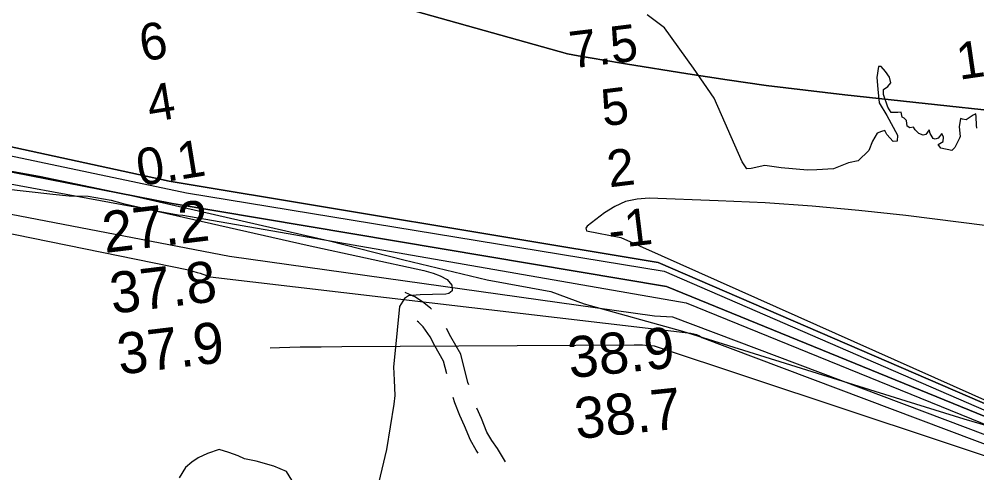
# Model space of a CAD drawing. Extents: x 3219052 to 3256913, y 800770 to 826146.
# Drawn here: x 3226376 to 3227938, y 812303 to 813043 of the extents above; entities that cross this region are included whole.
import ezdxf

# ---------------------------------------------------------------- set-up
doc = ezdxf.new("R2010")
doc.units = 0
for name, color, linetype in [('V-RIVR-EDGE', 7, 'Continuous'), ('V-RIVR-RANG', 7, 'Continuous'), ('V-ROAD-CNTR', 7, 'Continuous'), ('V-SITE-VEGE', 7, 'Continuous'), ('V-TOPO-DPTH', 7, 'Continuous'), ('V-TOPO-MAJR', 7, 'Continuous'), ('V-TOPO-MINR', 7, 'Continuous'), ('V-TOPO-WATR', 7, 'Continuous')]:
    doc.layers.add(name, color=color, linetype=linetype)

msp = doc.modelspace()

# ---------------------------------------------------------------- linework, layer by layer
at = {"layer": 'V-RIVR-EDGE'}
for points in [[(3227676.5, 812797.1), (3227661.4, 812796.4), (3227618.4, 812800.4), (3227591.9, 812803.7), (3227569.3, 812799), (3227562.2, 812798.6), (3227554.7, 812809.7), (3227509.1, 812913.8), (3227475.7, 812962.9), (3227428, 813028.6), (3227400, 813050)], [(3227937.6, 812864.9), (3227937.2, 812870), (3227936.4, 812883.5), (3227935.6, 812888.2), (3227931.7, 812886.3), (3227920.2, 812878.4), (3227913.9, 812879.6), (3227911.1, 812880.8), (3227908.7, 812866.9), (3227910.2, 812851.1), (3227909.4, 812848.4), (3227901.5, 812833.4), (3227896.7, 812828.2), (3227879, 812832.2), (3227874.6, 812838.2), (3227882.5, 812843.3), (3227883, 812850.4), (3227880.2, 812855.9), (3227874.7, 812848.4), (3227869.5, 812846.9), (3227866.4, 812848.1), (3227861.6, 812856), (3227859.7, 812862.3), (3227854.5, 812854.4), (3227850.2, 812853.6), (3227843, 812856), (3227836.7, 812862.4), (3227834, 812866.7), (3227828, 812865.6), (3227823.7, 812868.3), (3227822.9, 812877.4), (3227819, 812881), (3227815.8, 812883), (3227814.3, 812890.9), (3227808.7, 812890.5), (3227797.7, 812890.5), (3227792.2, 812898.9), (3227785.1, 812919.8), (3227785.5, 812928.1), (3227792.2, 812932.9), (3227797.4, 812938.8), (3227795, 812948.3), (3227788.7, 812957.4), (3227781.3, 812965.7), (3227776.9, 812965.3), (3227774.5, 812947.5), (3227776, 812928.5), (3227778.3, 812906), (3227790.9, 812885.4), (3227808.3, 812853.3), (3227807.4, 812843.5), (3227801.1, 812843.1), (3227790.9, 812854.6), (3227787.3, 812860.9), (3227781.8, 812859.7), (3227774.7, 812856.6), (3227767.1, 812843.6), (3227761.1, 812828.6), (3227744.1, 812811.6), (3227728.3, 812808.1), (3227703.7, 812798.3), (3227676.5, 812797.1)], [(3226287.4, 812808.3), (3226409, 812786.3), (3226552, 812756.4), (3226882.1, 812681.3), (3227002.9, 812650.1), (3227138.9, 812617.2), (3227242.7, 812598.2), (3227297.4, 812578.1), (3227457.7, 812533.8), (3227565.9, 812500), (3227821.7, 812420.3), (3227916.4, 812390.5), (3228037.6, 812355.4)]]:
    msp.add_lwpolyline(points, dxfattribs=at)
at = {"layer": 'V-ROAD-CNTR'}
for points in [[(3227048.1, 812569.7), (3227046.7, 812571.1), (3227033.6, 812581.6), (3227021.3, 812589.6), (3227012.5, 812593.7), (3227005.3, 812597)], [(3227073.1, 812464.3), (3227067.8, 812484.9), (3227053.7, 812509.8), (3227045.8, 812524.5), (3227034.9, 812540.6), (3227026.8, 812548.6), (3227024.8, 812550.2)], [(3227108.9, 812446), (3227107.6, 812450.1), (3227095.9, 812496.2), (3227079.9, 812524.3), (3227072.5, 812538.2)], [(3227124.5, 812334.8), (3227121.3, 812339.5), (3227111.7, 812355.7), (3227102.2, 812379.5), (3227094.7, 812396.1), (3227086.3, 812416.9), (3227083.7, 812425.7)], [(3227169.1, 812320.3), (3227155.7, 812342.4), (3227146.7, 812355.6), (3227138.7, 812369), (3227129.8, 812391.2), (3227122.3, 812407.9), (3227122.2, 812408.3)]]:
    msp.add_lwpolyline(points, dxfattribs=at)
at = {"layer": 'V-SITE-VEGE'}
for points in [[(3226227.4, 812779.9), (3226431, 812757.3), (3226457.6, 812754.6), (3226488.4, 812754), (3226526.1, 812747.3), (3226545.6, 812741.9), (3226845.6, 812674.1), (3227036, 812632.9), (3227051.1, 812628.6), (3227062.3, 812624.2), (3227073.8, 812618.2), (3227081.3, 812608.6), (3227082, 812599.6), (3227076.4, 812594.9), (3227071.6, 812594.3), (3227049.8, 812593.4), (3227029.7, 812593.1), (3227010.8, 812591.1), (3227004.1, 812586.8), (3226995.9, 812574.2), (3226988.4, 812496.7), (3226986.2, 812475.4), (3226987.1, 812453.8), (3226988.4, 812428.9), (3226986.8, 812414.4), (3226974.8, 812340.7), (3226908.9, 812063.1)], [(3226702.1, 812340.7), (3226683.2, 812333.9), (3226667.7, 812327), (3226657.5, 812320.1), (3226647.2, 812311.5), (3226636.9, 812294.4)], [(3226820.5, 812290.9), (3226811.9, 812304.7), (3226791.3, 812313.3), (3226762.1, 812321.8), (3226743.2, 812325.3), (3226733, 812330.4), (3226717.5, 812335.6), (3226702.1, 812340.7)]]:
    msp.add_lwpolyline(points, dxfattribs=at)
at = {"layer": 'V-TOPO-DPTH'}
for points in [[(3226569.3, 813182.7), (3227270, 812986), (3227287.3, 812983), (3227313.3, 812978.4), (3227326.1, 812976.1), (3227338.9, 812973.9), (3227351.7, 812971.8), (3227364.6, 812969.7), (3227466.3, 812953.4), (3227530.1, 812943.7), (3227593.9, 812934.7), (3227657.9, 812926.6), (3227722, 812919.3), (3227984.1, 812891.2)], [(3226569.3, 813182.7), (3227270, 812986), (3227287.3, 812983), (3227313.3, 812978.4), (3227326.1, 812976.1), (3227338.9, 812973.9), (3227351.7, 812971.8), (3227364.6, 812969.7), (3227466.3, 812953.4), (3227530.1, 812943.7), (3227593.9, 812934.7), (3227657.9, 812926.6), (3227722, 812919.3), (3227984.1, 812891.2)], [(3230110.9, 811912.1), (3229345.3, 812028.2), (3229335.6, 812028.9), (3229325.9, 812029.6), (3229316.2, 812030.5), (3228840.2, 812160.3), (3228832.3, 812161.4), (3228824.4, 812162.6), (3228816.6, 812163.9), (3228808.8, 812165.3), (3228775.2, 812171.3), (3228039.4, 812378.3), (3228034.3, 812379.1), (3227418, 812645.9), (3226620.7, 812778.6), (3225840.2, 812948.1)], [(3225840.2, 812948.1), (3226620.7, 812778.6), (3227418, 812645.9), (3228034.3, 812379.1), (3228039.4, 812378.3), (3228775.2, 812171.3), (3228808.8, 812165.3), (3228816.6, 812163.9), (3228824.4, 812162.6), (3228832.3, 812161.4), (3228840.2, 812160.3), (3229316.2, 812030.5), (3229325.9, 812029.6), (3229335.6, 812028.9), (3229345.3, 812028.2), (3230110.9, 811912.1)], [(3228032.1, 812361.1), (3227431.6, 812606.6), (3226625.3, 812741.9), (3225785.4, 812906.7)]]:
    msp.add_lwpolyline(points, dxfattribs=at)
at = {"layer": 'V-TOPO-MAJR'}
msp.add_lwpolyline([(3225944.6, 812777.6), (3226652, 812633.6), (3226666.1, 812629.6), (3226670.8, 812628.1), (3226687.1, 812622.6), (3227470.9, 812530.3), (3227475.9, 812529.5), (3227480.6, 812528.2), (3227485, 812526), (3227489.2, 812523.2), (3228021.5, 812322.8), (3228050.8, 812318.3), (3228820.2, 812103.6), (3228831.7, 812101.8), (3228843.1, 812099.9), (3228854.5, 812098), (3228892, 812091.6), (3228899.2, 812089.9), (3228906.2, 812087.6), (3229339.2, 811975.1), (3229374.3, 811972), (3230137.7, 811820.9)], dxfattribs=at)
at = {"layer": 'V-TOPO-MINR'}
for points in [[(3225849.1, 812928), (3226648.9, 812759.2), (3227427.4, 812631.6), (3228026.7, 812371.8), (3228036.1, 812370.5), (3228799.7, 812156.6), (3228812.7, 812154.4), (3228825.7, 812152.3), (3229306.9, 812021.4), (3229321.6, 812020.1), (3230083.9, 811899.6)], [(3225785.4, 812906.7), (3226625.3, 812741.9), (3227431.6, 812606.6), (3228032.1, 812361.1)], [(3225898.3, 812859.3), (3226635.1, 812723.4), (3226642.6, 812723.2), (3227463.5, 812579.9), (3228027.5, 812350.3), (3228779.1, 812136.6), (3228803.8, 812132.6), (3229337.7, 811997.9), (3230053.5, 811870.9)], [(3225848.2, 812823.4), (3226719.1, 812656.3), (3227412, 812558.8), (3227441.3, 812556.9), (3228022.2, 812337.8), (3228793.6, 812121.3), (3228811.8, 812118.4), (3228830, 812115.5), (3228848.2, 812112.5), (3228866.4, 812109.5), (3229338.4, 811986.8), (3230098.6, 811849)], [(3227997.8, 812700.3), (3227821.5, 812722.3), (3227745.3, 812730.8), (3227668.9, 812737.9), (3227592.4, 812743), (3227515.8, 812746.6), (3227403.1, 812750.5), (3227383.4, 812749.1), (3227364.6, 812745.1), (3227347, 812737.3), (3227330.3, 812727), (3227302.2, 812705.2), (3227300.9, 812703.5), (3227300.1, 812701.7), (3227300.2, 812699.7), (3227300.9, 812697.6), (3227357, 812686.3), (3228025.8, 812388)], [(3226785.4, 812506.6), (3226800.3, 812507.1), (3226834.2, 812507.9), (3226868.2, 812508.4), (3226902.1, 812508.7), (3227378.7, 812511.6), (3227383.3, 812511.5), (3227387.9, 812511.5), (3227392.5, 812511.3), (3227397.1, 812511), (3227411.2, 812510), (3228029.7, 812304.3)]]:
    msp.add_lwpolyline(points, dxfattribs=at)
at = {"layer": 'V-TOPO-WATR'}
for points in [[(3227984.1, 812891.2), (3227722, 812919.3), (3227657.9, 812926.6), (3227593.9, 812934.7), (3227530.1, 812943.7), (3227466.3, 812953.4), (3227364.6, 812969.7), (3227351.7, 812971.8), (3227338.9, 812973.9), (3227326.1, 812976.1), (3227313.3, 812978.4), (3227287.3, 812983), (3227270, 812986), (3226569.3, 813182.7)], [(3225840.2, 812948.1), (3226620.7, 812778.6), (3227418, 812645.9), (3228034.3, 812379.1), (3228039.4, 812378.3), (3228775.2, 812171.3), (3228808.8, 812165.3), (3228816.6, 812163.9), (3228824.4, 812162.6), (3228832.3, 812161.4), (3228840.2, 812160.3), (3229316.2, 812030.5), (3229325.9, 812029.6), (3229335.6, 812028.9), (3229345.3, 812028.2), (3230110.9, 811912.1)]]:
    msp.add_lwpolyline(points, dxfattribs=at)

# ---------------------------------------------------------------- texts
at = {"layer": 'V-RIVR-RANG'}
for s, height, rotation, p in [('6', 60, 9.1991, (3226577, 812973.5)), ('7.5', 60, 6.9954, (3227276.7, 812962.1)), ('10.6', 60, 8.2697, (3227908.9, 812943.7)), ('4', 60, 9.1991, (3226589.5, 812874.3)), ('5', 60, 6.9954, (3227328.5, 812867.8)), ('0.1', 60, 9.1991, (3226572.4, 812770.3)), ('2', 60, 6.9954, (3227338.2, 812768.2)), ('27.2', 67, 6.9283, (3226515.6, 812661.1)), ('-1', 60, 6.9954, (3227340, 812667.7)), ('37.8', 67, 6.9283, (3226527.9, 812561.9)), ('37.9', 67, 6.9283, (3226539.9, 812462.6)), ('38.9', 67, 5.9083, (3227274, 812456.9)), ('38.7', 67, 5.9083, (3227284.8, 812357.5))]:
    msp.add_text(s, height=height, rotation=rotation, dxfattribs=at).set_placement(p)

doc.saveas('drawing.dxf')
